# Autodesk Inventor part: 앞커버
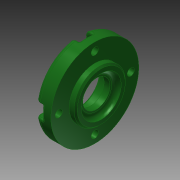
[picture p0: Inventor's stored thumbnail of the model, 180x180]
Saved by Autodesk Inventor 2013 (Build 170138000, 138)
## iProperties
Created: 2015-11
Part Number: 앞커버
Material: 알루미늄 6061
Document SubType Name: Modeling
Designer: mduedu
Density: 1 g/cm^3
Author: mduedu
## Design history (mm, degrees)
sketch "스케치1"
  geometry: L1 (-7, 0)-(7, 0); L2 (-7, 0)-(-7, 27.5); L3 (-7, 27.5)-(3, 27.5); L4 (3, 27.5)-(3, 16); L5 (3, 16)-(7, 16); L6 (7, 16)-(7, 0); 2 further points
  constraints: 12 end point, 3 perpendicular, 2 parallel, 1 coincident, 1 horizontal, 1 midpoint
  dimensions: "d0" = 14 distance of L1.start L1.end; "d1" = 55 diameter of L3 L1; "d2" = 4 distance of L4.end L5.end; "d3" = 32 diameter of L5 L1
revolve "회전1" sketch "스케치1" stored, may be unused: angle "d4" = 90 deg
hole "구멍1" diameter "d7" = 25; stored, may be unused: countersink angle "d11" = 90 deg, drill point angle "d13" = 0 deg; dims "d5" = 10, "d6" = 10, "d8" = 6, "d9" = 4, "d10" = 2, "d12" = 3
hole "구멍2" diameter "d16" = 25; stored, may be unused: countersink angle "d20" = 90 deg, drill point angle "d22" = 0 deg; dims "d17" = 6, "d18" = 4, "d19" = 2, "d21" = 7.3, "d61" = 10, "d62" = 10
hole "구멍3" diameter "d25" = 17; stored, may be unused: countersink angle "d29" = 90 deg, drill point angle "d31" = 0 deg; dims "d23" = 10, "d24" = 10, "d26" = 6, "d27" = 4, "d28" = 2, "d30" = 4.2
chamfer "모따기1" distance "d32" = 0.7; stored, may be unused: second distance "d33" = 2, angle "d34" = 30 deg
fillet "모깎기1" dims "d35" = 0.3
fillet "모깎기2" dims "d36" = 3
fillet "모깎기3" dims "d37" = 3
sketch "스케치2" dims "d39" = 45
  geometry: C1 r 12.904 at (0, 0) reference; C2 r 24.5 at (0, 0) reference; 6 further points
  constraints: 2 vertical alignment, 1 coincident, 7 other
  dimensions: "d42" = 360 deg dimension on point (0, 0) point (0, 22.5) (derived)
sketch "스케치3"
  geometry: 8 further points
  constraints: 4 coincident
hole "구멍4" sketch "스케치3" at (-22.5, 0), (0, -22.5), (22.5, 0), (0, 22.5) diameter "d44" = 4.5; stored, may be unused: countersink angle "d48" = 90 deg, drill point angle "d50" = 0 deg; dims "d45" = 6, "d46" = 8, "d47" = 4.6, "d49" = 8
sketch "스케치4"
  geometry: L1 (-4, 0)-(-4, -4.708); L2 (4, 0)-(4, -4.708); A1 r 4 centre (0, 0) between (-4, 0) and (4, 0) reference; A2 r 27.5 centre (0, 22.5) between (-4, -4.708) and (4, -4.708) reference; 3 further points
  constraints: 4 end point, 4 point on circle, 2 tangent, 1 parallel, 1 vertical
extrude "돌출1" cut sketch "스케치4" stored distance "d51" = 0; taper "d52" = 0 deg
fillet "모깎기5" dims "d56" = 0.3
fillet "모깎기6" dims "d57" = 1
chamfer "모따기2" distance "d63" = 1; stored, may be unused: second distance "d64" = 2, angle "d65" = 45 deg
node "솔리드1"
pattern_circular "원형 패턴1" dims angle "d54" = 360 deg
